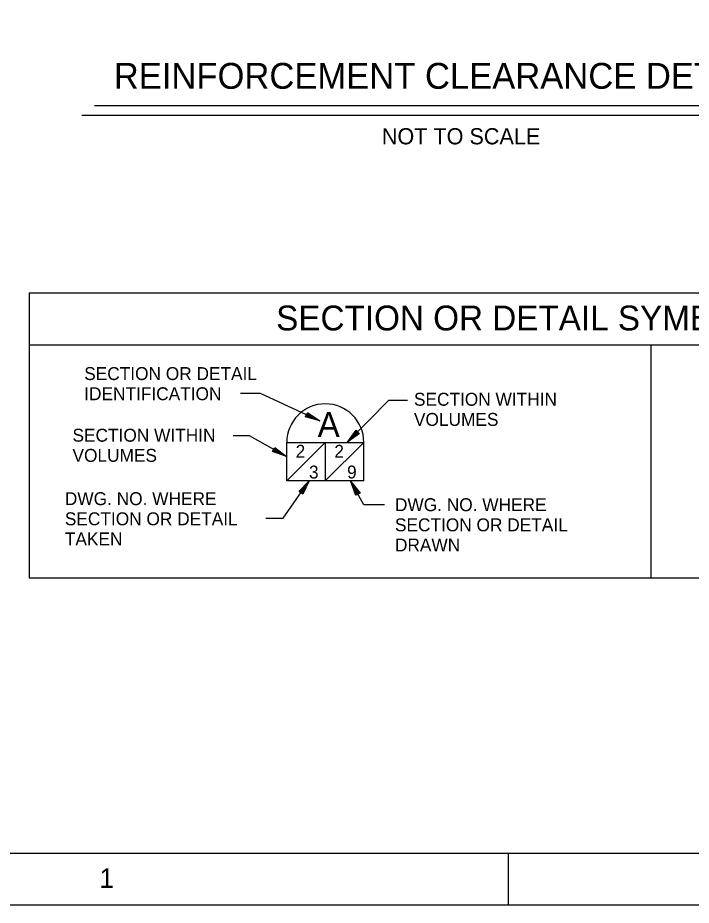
# Model space of a CAD drawing. Extents: x 22369.62 to 22373.29, y 22369.62 to 22372.46.
# Drawn here: x 22370.004 to 22370.546, y 22369.621 to 22370.335 of the extents above; entities that cross this region are included whole.
import ezdxf

# ---------------------------------------------------------------- set-up
doc = ezdxf.new("R2010")
doc.units = 0
for name, color, linetype in [('Level 1', 7, 'Continuous'), ('Level 10', 7, 'Continuous'), ('Level 3', 7, 'Continuous'), ('Level 4', 7, 'Continuous'), ('Level 50', 7, 'Continuous'), ('Level 9', 7, 'Continuous')]:
    doc.layers.add(name, color=color, linetype=linetype)

msp = doc.modelspace()

# ---------------------------------------------------------------- linework, layer by layer
at = {"layer": 'Level 1'}
for p, q in [((22370.24428, 22370.01231), (22370.24428, 22370.01231)), ((22370.24723, 22370.01095), (22370.24723, 22370.01095)), ((22370.27189, 22369.996), (22370.27189, 22369.996)), ((22370.26961, 22369.99368), (22370.26961, 22369.99368)), ((22370.21756, 22369.98378), (22370.21756, 22369.98378)), ((22370.22039, 22369.98219), (22370.22039, 22369.98219)), ((22370.23675, 22369.95989), (22370.23675, 22369.95989)), ((22370.2386, 22369.96256), (22370.2386, 22369.96256)), ((22370.27214, 22369.96205), (22370.27214, 22369.96205)), ((22370.27376, 22369.95923), (22370.27376, 22369.95923))]:
    msp.add_line(p, q, dxfattribs=at)
msp.add_lwpolyline([(22369.6213, 22372.4553), (22373.288, 22372.4553), (22373.288, 22369.6213), (22369.6213, 22369.6213)], close=True, dxfattribs=at)
for points in [[(22370.18344, 22370.03307), (22370.19933, 22370.03307), (22370.24723, 22370.01095)], [(22370.31786, 22370.02723), (22370.30256, 22370.02723), (22370.26961, 22369.99368)], [(22370.23742, 22370.0176), (22370.24723, 22370.01095), (22370.2358, 22370.01409), (22370.23719, 22370.01709), (22370.24428, 22370.01231), (22370.23652, 22370.01445), (22370.23741, 22370.01637), (22370.24143, 22370.01362), (22370.23724, 22370.0148), (22370.2376, 22370.0156), (22370.23849, 22370.01498)], [(22370.27918, 22370.00065), (22370.26961, 22369.99368), (22370.27641, 22370.00337), (22370.27878, 22370.00105), (22370.27189, 22369.996), (22370.27652, 22370.00258), (22370.27803, 22370.00109), (22370.27408, 22369.99823), (22370.27661, 22370.00178), (22370.27724, 22370.00116), (22370.27635, 22370.00054)], [(22370.17763, 22369.99905), (22370.19031, 22369.99905), (22370.22039, 22369.98219)], [(22370.21114, 22369.98959), (22370.22039, 22369.98219), (22370.20925, 22369.98621), (22370.21087, 22369.9891), (22370.21756, 22369.98378), (22370.21, 22369.98651), (22370.21103, 22369.98836), (22370.21483, 22369.9853), (22370.21074, 22369.98681), (22370.21116, 22369.98757), (22370.212, 22369.98689)], [(22370.2037, 22369.9326), (22370.21783, 22369.9326), (22370.2386, 22369.96256)], [(22370.23035, 22369.95406), (22370.2386, 22369.96256), (22370.23354, 22369.95185), (22370.23081, 22369.95374), (22370.23675, 22369.95989), (22370.23331, 22369.95262), (22370.23156, 22369.95383), (22370.23496, 22369.95732), (22370.23308, 22369.95338), (22370.23236, 22369.95388), (22370.23312, 22369.95465)], [(22370.29943, 22369.94346), (22370.28278, 22369.94346), (22370.27214, 22369.96205)], [(22370.27627, 22369.95095), (22370.27214, 22369.96205), (22370.27963, 22369.95286), (22370.27675, 22369.95123), (22370.27376, 22369.95923), (22370.27884, 22369.95299), (22370.277, 22369.95194), (22370.27531, 22369.95652), (22370.27805, 22369.95311), (22370.27729, 22369.95268), (22370.27692, 22369.9537)]]:
    msp.add_lwpolyline(points, dxfattribs=at)
at = {"layer": 'Level 10'}
for p, q in [((22370.06599, 22370.26462), (22370.66363, 22370.26462)), ((22370.05582, 22370.25684), (22370.67561, 22370.25684)), ((22370.01348, 22370.11382), (22370.01348, 22369.88465)), ((22370.01348, 22370.11382), (22370.84681, 22370.11382)), ((22370.01348, 22370.07215), (22370.84681, 22370.07215)), ((22370.51348, 22370.07215), (22370.51348, 22369.88465)), ((22370.01348, 22369.88465), (22370.84681, 22369.88465)), ((22370.399, 22369.6213), (22370.399, 22369.6633))]:
    msp.add_line(p, q, dxfattribs=at)
at = {"layer": 'Level 3'}
for p, q in [((22370.22066, 22369.99356), (22370.28266, 22369.99356)), ((22370.22066, 22369.96256), (22370.22066, 22369.99356)), ((22370.25166, 22369.99356), (22370.25166, 22369.96256)), ((22370.28266, 22369.96256), (22370.28266, 22369.99356)), ((22370.28266, 22369.96256), (22370.22066, 22369.96256))]:
    msp.add_line(p, q, dxfattribs=at)
msp.add_arc((22370.25166, 22369.99356), 0.031, 0, 180, dxfattribs=at)
at = {"layer": 'Level 50'}
for p, q in [((22370.22066, 22369.96256), (22370.25166, 22369.99356)), ((22370.25166, 22369.96256), (22370.28266, 22369.99356))]:
    msp.add_line(p, q, dxfattribs=at)
at = {"layer": 'Level 9'}
msp.add_line((22369.7463, 22369.6633), (22373.017, 22369.6633), dxfattribs=at)

# ---------------------------------------------------------------- texts
at = {"layer": 'Level 1'}
msp.add_text('1', height=0.01561, dxfattribs=at).set_placement((22370.07, 22369.6353))
at = {"layer": 'Level 3'}
for s, height, p in [('REINFORCEMENT CLEARANCE DETAIL', 0.0208021, (22370.08151, 22370.27797)), ('SECTION OR DETAIL SYMBOL', 0.02, (22370.21215, 22370.08362)), ('A', 0.02, (22370.24549, 22369.9979))]:
    msp.add_text(s, height=height, dxfattribs=at).set_placement(p)
at = {"layer": 'Level 4'}
for s, height, p in [('NOT TO SCALE', 0.013, (22370.29715, 22370.23328)), ('SECTION OR DETAIL', 0.0103958, (22370.05769, 22370.04371)), ('IDENTIFICATION', 0.0103958, (22370.05769, 22370.02751)), ('SECTION WITHIN', 0.0103958, (22370.32299, 22370.02305)), ('VOLUMES', 0.010396, (22370.32299, 22370.00685)), ('SECTION WITHIN', 0.0103958, (22370.04827, 22369.99413)), ('VOLUMES', 0.010396, (22370.04827, 22369.97794)), ('2', 0.0104, (22370.22779, 22369.9812)), ('2', 0.0104, (22370.25892, 22369.9812)), ('3', 0.0104, (22370.23855, 22369.96453)), ('9', 0.0104, (22370.26918, 22369.96453)), ('DWG. NO. WHERE', 0.0103958, (22370.04213, 22369.94311)), ('DWG. NO. WHERE', 0.0103958, (22370.3077, 22369.93826)), ('SECTION OR DETAIL', 0.0103958, (22370.04213, 22369.92691)), ('SECTION OR DETAIL', 0.0103958, (22370.3077, 22369.92206)), ('TAKEN', 0.010396, (22370.04213, 22369.91072)), ('DRAWN', 0.010396, (22370.3077, 22369.90586))]:
    msp.add_text(s, height=height, dxfattribs=at).set_placement(p)

doc.saveas('drawing.dxf')
